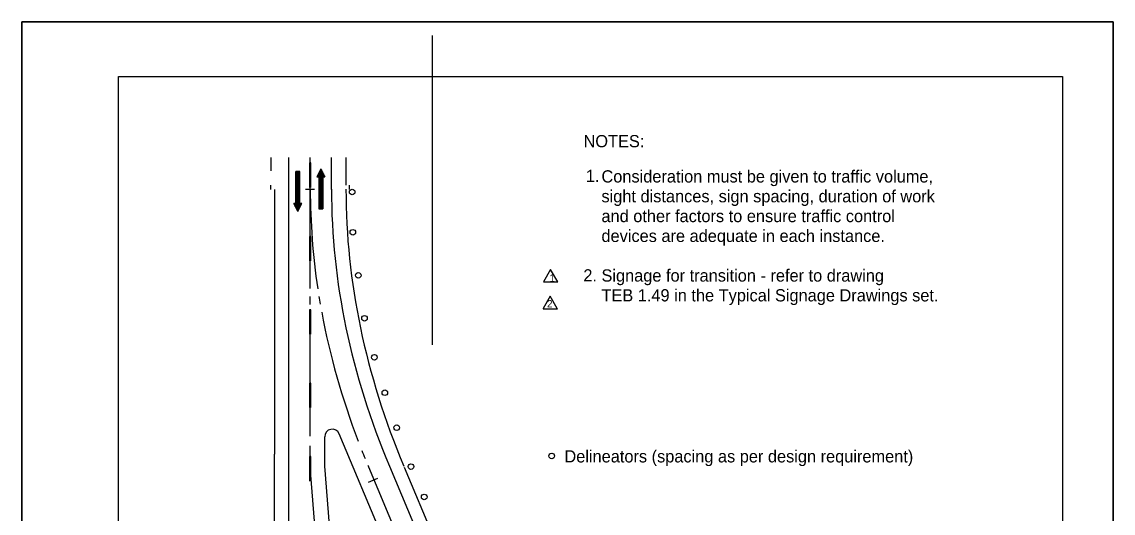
# Model space of a CAD drawing. Extents: x 1806 to 2022, y 110 to 389.
# Drawn here: x 1805.6 to 2021.6, y 292 to 389.2 of the extents above; entities that cross this region are included whole.
import ezdxf

# ---------------------------------------------------------------- set-up
doc = ezdxf.new("R2010")
doc.units = 0
for name, color, linetype in [('Level 1', 7, 'Continuous'), ('Level 10', 7, 'Continuous'), ('Level 2', 7, 'Continuous'), ('Level 3', 7, 'Continuous'), ('Level 44', 7, 'Continuous'), ('Level 60', 7, 'Continuous'), ('Level 63', 7, 'Continuous'), ('Level 7', 7, 'Continuous')]:
    doc.layers.add(name, color=color, linetype=linetype)

msp = doc.modelspace()

# ---------------------------------------------------------------- linework, layer by layer
at = {"layer": 'Level 1'}
msp.add_lwpolyline([(1910.25, 340.22), (1908.83, 337.75), (1911.67, 337.75)], close=True, dxfattribs=at)
at = {"layer": 'Level 10'}
for p, q in [((1859.82, 353.25), (1859.82, 359.56)), ((1860.61, 359.56), (1859.82, 359.56)), ((1859.82, 352.46), (1859.82, 359.56)), ((1859.92, 352.26), (1859.92, 359.56)), ((1860.02, 352.07), (1860.02, 359.56)), ((1860.12, 351.87), (1860.12, 359.56)), ((1860.21, 351.67), (1860.21, 359.56)), ((1860.31, 351.87), (1860.31, 359.56)), ((1860.41, 352.07), (1860.41, 359.56)), ((1860.51, 352.26), (1860.51, 359.56)), ((1860.61, 353.25), (1860.61, 359.56)), ((1860.61, 352.46), (1860.61, 359.56)), ((1864.78, 360.1), (1863.99, 358.52)), ((1864.09, 358.72), (1864.09, 358.52)), ((1864.19, 358.92), (1864.19, 358.52)), ((1864.29, 359.11), (1864.29, 358.52)), ((1864.38, 359.31), (1864.38, 352.22)), ((1864.48, 359.51), (1864.48, 352.22)), ((1864.58, 359.71), (1864.58, 352.22)), ((1864.68, 359.9), (1864.68, 352.22)), ((1864.78, 360.1), (1864.78, 352.22)), ((1864.78, 360.1), (1865.57, 358.52)), ((1864.88, 359.9), (1864.88, 352.22)), ((1864.98, 359.71), (1864.98, 352.22)), ((1865.08, 359.51), (1865.08, 352.22)), ((1865.17, 359.31), (1865.17, 352.22)), ((1865.27, 359.11), (1865.27, 358.52)), ((1865.37, 358.92), (1865.37, 358.52)), ((1865.47, 358.72), (1865.47, 358.52)), ((1863.99, 358.52), (1864.38, 358.52)), ((1864.38, 358.52), (1864.38, 352.22)), ((1865.17, 358.52), (1865.17, 352.22)), ((1865.17, 358.52), (1865.57, 358.52)), ((1860.21, 351.67), (1859.43, 353.25)), ((1859.82, 353.25), (1859.43, 353.25)), ((1859.53, 353.05), (1859.53, 353.25)), ((1859.62, 352.86), (1859.62, 353.25)), ((1859.72, 352.66), (1859.72, 353.25)), ((1860.21, 351.67), (1861, 353.25)), ((1861, 353.25), (1860.61, 353.25)), ((1860.71, 352.66), (1860.71, 353.25)), ((1860.81, 352.86), (1860.81, 353.25)), ((1860.9, 353.05), (1860.9, 353.25)), ((1864.38, 352.22), (1865.17, 352.22))]:
    msp.add_line(p, q, dxfattribs=at)
at = {"layer": 'Level 2'}
for p, q in [((1886.87, 325.33), (1886.87, 386.49)), ((1858.46, 138.73), (1858.46, 362.35)), ((1862.52, 361.28), (1862.52, 356.44)), ((1862.81, 361.28), (1862.52, 361.28)), ((1862.81, 356.44), (1862.81, 361.28)), ((1866.86, 356.06), (1866.86, 362.35)), ((1862.52, 346.76), (1862.52, 341.93)), ((1862.81, 346.76), (1862.52, 346.76)), ((1862.81, 341.93), (1862.81, 346.76)), ((1862.52, 332.25), (1862.52, 327.41)), ((1862.81, 332.25), (1862.52, 332.25)), ((1862.81, 327.41), (1862.81, 332.25)), ((1862.52, 317.74), (1862.52, 312.9)), ((1862.81, 317.74), (1862.52, 317.74)), ((1862.81, 312.9), (1862.81, 317.74)), ((1862.52, 303.22), (1862.52, 298.38)), ((1862.81, 303.22), (1862.52, 303.22)), ((1862.81, 298.38), (1862.81, 303.22)), ((1866.86, 248.69), (1862.66, 301.19)), ((1874.18, 301.19), (1883.41, 279.23)), ((1878.36, 301.3), (1896.74, 257.55))]:
    msp.add_line(p, q, dxfattribs=at)
for points in [[(1862.66, 336.43), (1862.66, 362.35)], [(1862.66, 333.32), (1862.66, 334.88)], [(1862.66, 307.23), (1862.66, 331.77)], [(1862.66, 303.27), (1862.66, 305.32)]]:
    msp.add_lwpolyline(points, dxfattribs=at)
for major_axis, start_param, end_param in [((-2099.98, 0), 6.283185, 6.320629), ((-2095.79, 0), 6.283185, 6.387906), ((-2099.98, 0), 0.040329, 0.043237), ((-2099.98, 0), 0.046327, 0.095008), ((-2099.98, 0), 0.098529, 0.101621), ((-2099.98, 0), 0.104052, 0.10472)]:
    msp.add_ellipse((3962.66, 356.07), major_axis=major_axis, ratio=0.25, start_param=start_param, end_param=end_param, dxfattribs=at)
at = {"layer": 'Level 3'}
for centre in [(1870.97, 355.53), (1871.1, 347.57), (1872.18, 339.06), (1873.41, 330.56), (1875.37, 322.86), (1877.43, 315.85), (1879.79, 308.93), (1910.46, 303.34), (1882.61, 301.24), (1885.23, 295.24)]:
    msp.add_circle(centre, 0.552, dxfattribs=at)
at = {"layer": 'Level 60'}
for p, q in [((1805.59, 389.18), (1805.59, 389.18)), ((2021.59, 389.18), (1805.59, 389.18)), ((1805.59, 389.18), (1805.59, 110.17)), ((2021.59, 110.18), (2021.59, 389.18))]:
    msp.add_line(p, q, dxfattribs=at)
for points in [[(1805.59, 389.18), (2021.59, 389.18), (2021.59, 110.18), (1805.59, 110.18)], [(1824.71, 378.37), (2011.59, 378.37), (2011.59, 120.98), (1824.71, 120.98)]]:
    msp.add_lwpolyline(points, close=True, dxfattribs=at)
at = {"layer": 'Level 63'}
for points in [[(1910.17, 334.92), (1908.78, 332.49)], [(1911.57, 332.49), (1910.17, 334.92)], [(1908.78, 332.49), (1908.75, 332.45), (1911.59, 332.45), (1911.57, 332.49)]]:
    msp.add_lwpolyline(points, dxfattribs=at)
at = {"layer": 'Level 7'}
for p, q in [((1854.86, 362.35), (1854.86, 359.69)), ((1869.73, 362.35), (1869.73, 356.89)), ((1854.86, 356.04), (1854.86, 356.89)), ((1870.46, 356.06), (1870.46, 356.89)), ((1855.59, 356.04), (1855.59, 303.67)), ((1861.7, 356.07), (1863.51, 356.07)), ((1889.58, 257.38), (1868.41, 307.71)), ((1855.59, 246.06), (1855.59, 303.67)), ((1869.73, 248.81), (1865.53, 301.31)), ((1881.26, 301.11), (1899.65, 257.38)), ((1874.21, 298.15), (1876.08, 298.93))]:
    msp.add_line(p, q, dxfattribs=at)
msp.add_lwpolyline([(1865.53, 301.31), (1865.53, 307.13)], dxfattribs=at)
msp.add_arc((1867.03, 307.13), 1.5, 22.8108, 180, dxfattribs=at)
msp.add_ellipse((3962.66, 356.07), major_axis=(-2092.92, 0), ratio=0.250262, start_param=6.283185, end_param=6.387906, dxfattribs=at)

# ---------------------------------------------------------------- texts
at = {"layer": 'Level 1'}
msp.add_text('1', height=1.45, rotation=360, dxfattribs=at).set_placement((1910.02, 337.8))
at = {"layer": 'Level 10'}
for s, p in [('NOTES:', (1916.76, 364.38)), ('1.', (1917.23, 357.52)), ('Consideration must be given to traffic volume,', (1920.31, 357.41)), ('sight distances, sign spacing, duration of work', (1920.31, 353.49)), ('and other factors to ensure traffic control ', (1920.31, 349.57)), ('devices are adequate in each instance.', (1920.31, 345.65)), ('2.', (1916.72, 337.84)), ('Signage for transition - refer to drawing ', (1920.31, 337.82)), ('TEB 1.49 in the Typical Signage Drawings set.', (1920.31, 333.9)), ('Delineators (spacing as per design requirement)', (1912.98, 302.06))]:
    msp.add_text(s, height=2.419, dxfattribs=at).set_placement(p)
at = {"layer": 'Level 44'}
msp.add_text('2', height=1.45, rotation=360, dxfattribs=at).set_placement((1909.54, 332.72))

doc.saveas('drawing.dxf')
